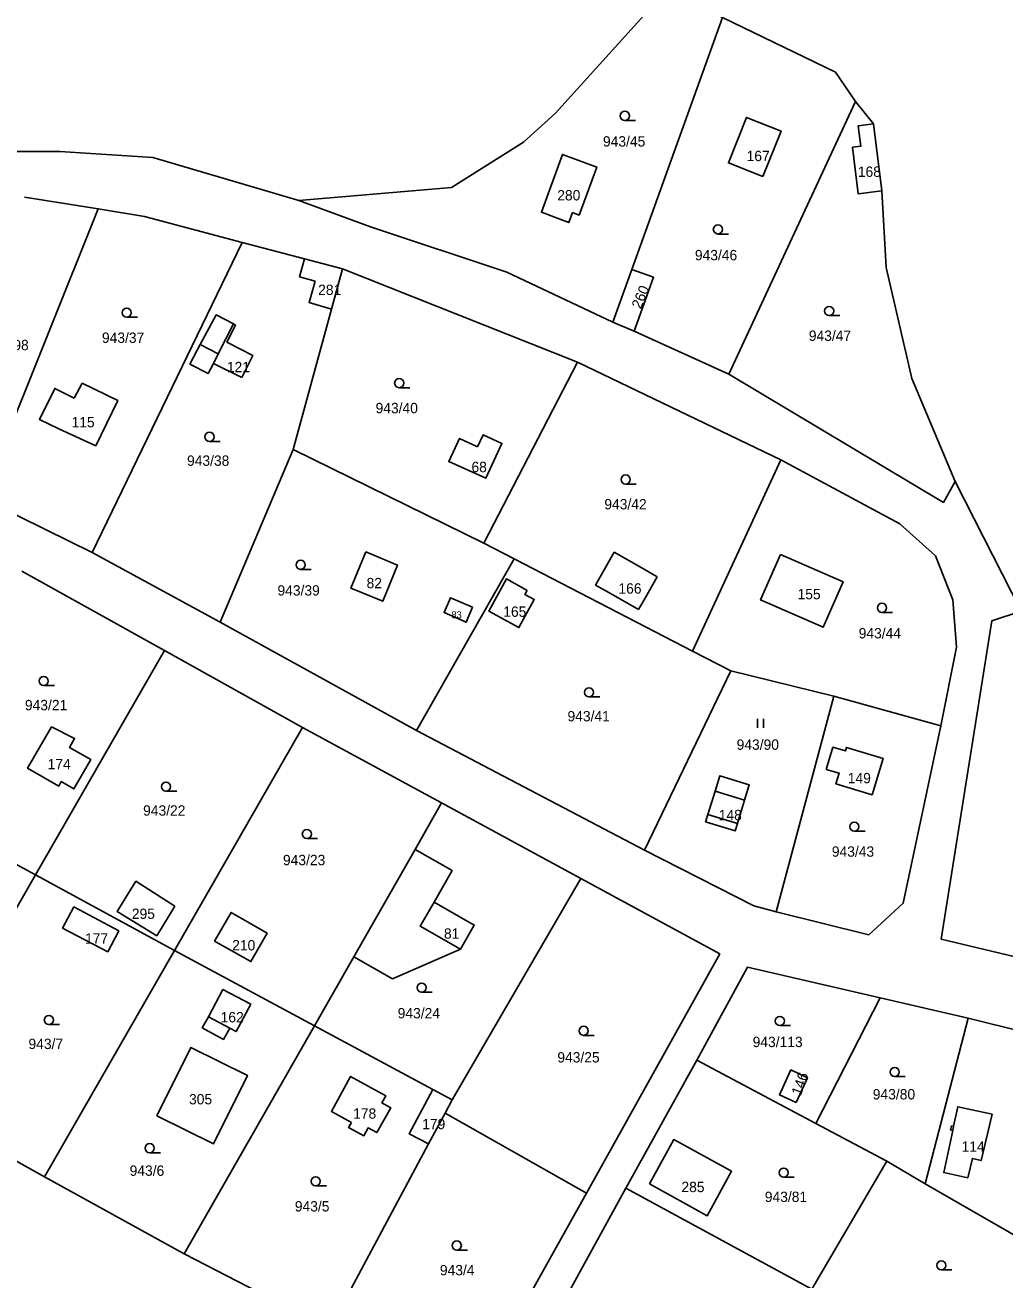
# Model space of a CAD drawing. Extents: x -7476540 to -746055, y -11317203 to -1129777.
# Drawn here: x -750806.6 to -750645.6, y -1131103.6 to -1130897.4 of the extents above; entities that cross this region are included whole.
import ezdxf

# ---------------------------------------------------------------- set-up
doc = ezdxf.new("R2010")
doc.units = 0
for name, color, linetype in [('Hranice parcel', 7, 'Continuous'), ('Parcelní čísla', 7, 'Continuous'), ('Vnitřní kresba', 7, 'Continuous'), ('Značky kultur', 7, 'Continuous')]:
    doc.layers.add(name, color=color, linetype=linetype)

msp = doc.modelspace()

# ---------------------------------------------------------------- linework, layer by layer
at = {"layer": 'Hranice parcel'}
for p, q in [((-750706.94, -1130937.58), (-750692.03, -1130896.19)), ((-750690.96, -1130954.78), (-750670.18, -1130909.99)), ((-750670.18, -1130909.99), (-750667.24, -1130913.65)), ((-750665.85, -1130924.67), (-750667.24, -1130913.65)), ((-750806.68, -1130925.7), (-750794.6, -1130927.65)), ((-750794.6, -1130927.65), (-750813.68, -1130975.17)), ((-750795.61, -1130984.09), (-750770.94, -1130933.18)), ((-750760.71, -1130935.83), (-750770.94, -1130933.18)), ((-750761.51, -1130938.81), (-750760.71, -1130935.83)), ((-750760.71, -1130935.83), (-750754.45, -1130937.46)), ((-750754.45, -1130937.46), (-750756.27, -1130944.11)), ((-750715.82, -1130952.81), (-750754.45, -1130937.46)), ((-750706.94, -1130937.58), (-750710.06, -1130946.23)), ((-750758.93, -1130939.53), (-750761.51, -1130938.81)), ((-750762.58, -1130967.16), (-750756.27, -1130944.11)), ((-750710.06, -1130946.23), (-750706.56, -1130947.73)), ((-750706.56, -1130947.73), (-750690.96, -1130954.78)), ((-750731.22, -1130982.55), (-750715.82, -1130952.81)), ((-750682.42, -1130968.89), (-750715.82, -1130952.81)), ((-750774.54, -1130995.56), (-750762.58, -1130967.16)), ((-750731.22, -1130982.55), (-750762.58, -1130967.16)), ((-750696.93, -1131000.31), (-750682.42, -1130968.89)), ((-750653.79, -1130972.43), (-750642.94, -1130993.73)), ((-750813.68, -1130975.17), (-750795.61, -1130984.09)), ((-750726.28, -1130985.14), (-750731.22, -1130982.55)), ((-750795.61, -1130984.09), (-750774.54, -1130995.56)), ((-750742.3, -1131013.32), (-750726.28, -1130985.14)), ((-750696.93, -1131000.31), (-750726.28, -1130985.14)), ((-750783.73, -1131000.19), (-750807.12, -1130987.17)), ((-750774.54, -1130995.56), (-750742.3, -1131013.32)), ((-750804.91, -1131037.07), (-750783.73, -1131000.19)), ((-750761.01, -1131012.83), (-750783.73, -1131000.19)), ((-750690.68, -1131003.53), (-750696.93, -1131000.31)), ((-750704.84, -1131033.01), (-750690.68, -1131003.53)), ((-750690.68, -1131003.53), (-750673.71, -1131007.69)), ((-750673.71, -1131007.69), (-750683.19, -1131043.14)), ((-750656.17, -1131012.57), (-750673.71, -1131007.69)), ((-750782.06, -1131049.49), (-750761.01, -1131012.83)), ((-750738.17, -1131025.24), (-750761.01, -1131012.83)), ((-750742.3, -1131013.32), (-750704.84, -1131033.01)), ((-750673.91, -1131016.08), (-750675, -1131019.76)), ((-750804.91, -1131037.07), (-750827.77, -1131024.65)), ((-750742.53, -1131032.88), (-750738.17, -1131025.24)), ((-750715.32, -1131037.65), (-750738.17, -1131025.24)), ((-750742.53, -1131032.88), (-750752.59, -1131050.52)), ((-750804.91, -1131037.07), (-750826.11, -1131074)), ((-750782.06, -1131049.49), (-750804.91, -1131037.07)), ((-750736.43, -1131074.01), (-750715.32, -1131037.65)), ((-750782.06, -1131049.49), (-750803.42, -1131086.7)), ((-750759.06, -1131061.85), (-750782.06, -1131049.49)), ((-750759.06, -1131061.85), (-750752.59, -1131050.52)), ((-750666.13, -1131057.26), (-750676.67, -1131077.92)), ((-750666.13, -1131057.26), (-750651.64, -1131060.63)), ((-750651.64, -1131060.63), (-750658.73, -1131087.82)), ((-750759.06, -1131061.85), (-750780.46, -1131099.34)), ((-750739.59, -1131072.31), (-750759.06, -1131061.85)), ((-750707.9, -1131088.56), (-750696.26, -1131067.52)), ((-750676.67, -1131077.92), (-750696.26, -1131067.52)), ((-750736.43, -1131074.01), (-750739.59, -1131072.31)), ((-750826.11, -1131074), (-750803.42, -1131086.7)), ((-750736.43, -1131074.01), (-750737.61, -1131076.21)), ((-750737.61, -1131076.21), (-750740.31, -1131081.25)), ((-750714.39, -1131089.36), (-750737.61, -1131076.21)), ((-750676.67, -1131077.92), (-750665.04, -1131084.1)), ((-750740.31, -1131081.25), (-750756.59, -1131111.62)), ((-750677.36, -1131105.16), (-750665.04, -1131084.1)), ((-750665.04, -1131084.1), (-750658.73, -1131087.82)), ((-750803.42, -1131086.7), (-750780.46, -1131099.34)), ((-750658.73, -1131087.82), (-750635.2, -1131101.36)), ((-750719.53, -1131109.68), (-750707.9, -1131088.56)), ((-750707.9, -1131088.56), (-750677.36, -1131105.16)), ((-750780.46, -1131099.34), (-750756.59, -1131111.62))]:
    msp.add_line(p, q, dxfattribs=at)
for points in [[(-750761.64, -1130926.26), (-750736.55, -1130924.13), (-750724.71, -1130916.65), (-750719.47, -1130911.9), (-750701.35, -1130891.83), (-750692.03, -1130896.19)], [(-750692.03, -1130896.19), (-750673.46, -1130905.17), (-750670.18, -1130909.99)], [(-750904.82, -1130906.58), (-750890.06, -1130908.85), (-750861.88, -1130910.89), (-750825.89, -1130918.18), (-750800.92, -1130918.19), (-750785.63, -1130919.17), (-750761.64, -1130926.26)], [(-750685.37, -1130922.33), (-750682.41, -1130914.86), (-750688.1, -1130912.61), (-750691.05, -1130920.07), (-750685.37, -1130922.33)], [(-750667.24, -1130913.65), (-750669.72, -1130913.96), (-750669.29, -1130917.34), (-750670.67, -1130917.5), (-750669.76, -1130925.14), (-750665.85, -1130924.67)], [(-750716.69, -1130928.25), (-750715.58, -1130928.65), (-750712.69, -1130920.76), (-750718.33, -1130918.68), (-750721.78, -1130928.15), (-750717.29, -1130929.88), (-750716.69, -1130928.25)], [(-750665.85, -1130924.67), (-750665.13, -1130937.25), (-750660.92, -1130955.49), (-750653.79, -1130972.43)], [(-750761.64, -1130926.26), (-750749.88, -1130930.57), (-750727.47, -1130938.05), (-750710.06, -1130946.23)], [(-750770.94, -1130933.18), (-750786.99, -1130928.86), (-750794.6, -1130927.65)], [(-750706.56, -1130947.73), (-750703.36, -1130938.87), (-750706.94, -1130937.58)], [(-750756.27, -1130944.11), (-750759.96, -1130943), (-750758.93, -1130939.53)], [(-750771, -1130955.32), (-750769.19, -1130951.74), (-750773.46, -1130949.52), (-750772.03, -1130946.72), (-750772.39, -1130946.53), (-750775.21, -1130945.05), (-750777.82, -1130949.92), (-750779.54, -1130953.14), (-750776.54, -1130954.7), (-750775.66, -1130953.05), (-750771, -1130955.32)], [(-750690.96, -1130954.78), (-750655.74, -1130975.85), (-750653.79, -1130972.43)], [(-750798.55, -1130958.74), (-750798.68, -1130958.67), (-750801.74, -1130957.13), (-750804.24, -1130962.26), (-750801.04, -1130963.75), (-750795.01, -1130966.55), (-750791.39, -1130959.14), (-750797.23, -1130956.29), (-750798.55, -1130958.74)], [(-750732.25, -1130966.73), (-750735.23, -1130965.35), (-750737, -1130969.16), (-750730.9, -1130971.86), (-750728.26, -1130966.17), (-750731.33, -1130964.75), (-750732.25, -1130966.73)], [(-750656.17, -1131012.57), (-750653.56, -1130999.63), (-750654.19, -1130991.85), (-750657.02, -1130984.63), (-750662.89, -1130979.4), (-750682.42, -1130968.89)], [(-750750.65, -1130984), (-750753.08, -1130989.97), (-750747.85, -1130992.1), (-750745.43, -1130986.15), (-750750.65, -1130984)], [(-750702.74, -1130988.08), (-750705.39, -1130986.57), (-750709.81, -1130984.05), (-750712.87, -1130989.44), (-750710.72, -1130990.67), (-750705.8, -1130993.48)], [(-750682.52, -1130984.41), (-750685.78, -1130991.89), (-750675.46, -1130996.38), (-750672.21, -1130988.9), (-750682.52, -1130984.41)], [(-750724.09, -1130990.32), (-750727.53, -1130988.43), (-750730.43, -1130993.72), (-750725.48, -1130996.43), (-750722.95, -1130991.81), (-750724.48, -1130991.02), (-750724.09, -1130990.32)], [(-750705.8, -1130993.48), (-750704.66, -1130991.46), (-750703.45, -1130989.34), (-750702.74, -1130988.08)], [(-750733.11, -1130993.09), (-750736.72, -1130991.53), (-750737.78, -1130993.97), (-750734.13, -1130995.56), (-750733.11, -1130993.09)], [(-750642.94, -1130993.73), (-750647.77, -1130995.31), (-750656.09, -1131047.61), (-750622.78, -1131055.54)], [(-750802.29, -1131012.71), (-750798.48, -1131014.63), (-750799.33, -1131016.12), (-750795.83, -1131018.12), (-750798.58, -1131022.93), (-750800.66, -1131021.74), (-750801.08, -1131022.47), (-750806.2, -1131019.54), (-750802.29, -1131012.71)], [(-750683.19, -1131043.14), (-750667.98, -1131046.89), (-750662.32, -1131041.72), (-750656.17, -1131012.57)], [(-750675, -1131019.76), (-750672.85, -1131020.35), (-750673.39, -1131022.09), (-750667.46, -1131023.9), (-750665.65, -1131017.94), (-750671.64, -1131016.12), (-750671.81, -1131016.7), (-750673.91, -1131016.08)], [(-750694.79, -1131028.34), (-750689.92, -1131029.83), (-750689.56, -1131028.64), (-750688.39, -1131024.79), (-750687.62, -1131022.27), (-750692.47, -1131020.78), (-750693.25, -1131023.33), (-750694.42, -1131027.15), (-750694.79, -1131028.34)], [(-750752.59, -1131050.52), (-750746.25, -1131054.13), (-750735.08, -1131049.27), (-750732.82, -1131045.32), (-750739.42, -1131041.56), (-750736.45, -1131036.35), (-750742.53, -1131032.88)], [(-750683.19, -1131043.14), (-750686.87, -1131042.15), (-750704.84, -1131033.01)], [(-750782, -1131042.23), (-750784.98, -1131047.07), (-750791.46, -1131043.1), (-750788.41, -1131038.11), (-750782, -1131042.23)], [(-750714.39, -1131089.36), (-750692.47, -1131050.06), (-750715.32, -1131037.65)], [(-750798.61, -1131042.3), (-750800.45, -1131045.82), (-750793.02, -1131049.68), (-750791.23, -1131046.24), (-750798.61, -1131042.3)], [(-750775.51, -1131047.94), (-750769.51, -1131051.31), (-750766.84, -1131046.65), (-750772.73, -1131043.24), (-750775.51, -1131047.94)], [(-750696.26, -1131067.52), (-750687.94, -1131052.2), (-750666.13, -1131057.26)], [(-750777.52, -1131062.21), (-750774.03, -1131064.11), (-750772.97, -1131062.26), (-750771.94, -1131062.8), (-750769.53, -1131058.29), (-750774.13, -1131055.92), (-750776.5, -1131060.38), (-750777.52, -1131062.21)], [(-750635.2, -1131101.36), (-750630.48, -1131091.47), (-750623.21, -1131067.69), (-750651.64, -1131060.63)], [(-750784.95, -1131076.66), (-750779.37, -1131065.42), (-750770.09, -1131070), (-750775.67, -1131081.26), (-750784.95, -1131076.66)], [(-750679.91, -1131074.49), (-750682.68, -1131073.2), (-750680.78, -1131069.1), (-750678.05, -1131070.41), (-750679.91, -1131074.49)], [(-750752.99, -1131077.74), (-750753.45, -1131078.57), (-750750.97, -1131079.94), (-750750.25, -1131078.63), (-750748.84, -1131079.41), (-750746.51, -1131075.34), (-750747.99, -1131074.53), (-750747.34, -1131073.35), (-750753.13, -1131070.17), (-750756.29, -1131075.93), (-750752.99, -1131077.74)], [(-750739.59, -1131072.31), (-750743.52, -1131079.61), (-750740.31, -1131081.25)], [(-750647.72, -1131076.39), (-750653.36, -1131075.15), (-750654.05, -1131078.37), (-750654.39, -1131078.3), (-750654.54, -1131078.98), (-750654.19, -1131079.06)], [(-750654.19, -1131079.06), (-750655.67, -1131085.97), (-750651.73, -1131086.82), (-750650.97, -1131083.66), (-750649.55, -1131084), (-750647.72, -1131076.39)], [(-750704.03, -1131087.85), (-750694.53, -1131093.07), (-750690.52, -1131085.77), (-750700.04, -1131080.55), (-750704.03, -1131087.85)], [(-750756.59, -1131111.62), (-750759.02, -1131115.99), (-750736.32, -1131128.66), (-750714.39, -1131089.36)]]:
    msp.add_lwpolyline(points, dxfattribs=at)
at = {"layer": 'Vnitřní kresba'}
for p, q in [((-750774.87, -1130951.47), (-750772.39, -1130946.53)), ((-750777.82, -1130949.92), (-750774.87, -1130951.47)), ((-750775.66, -1130953.05), (-750774.87, -1130951.47)), ((-750693.25, -1131023.33), (-750688.39, -1131024.79)), ((-750694.42, -1131027.15), (-750689.56, -1131028.64)), ((-750772.97, -1131062.26), (-750776.5, -1131060.38)), ((-750654.05, -1131078.37), (-750654.19, -1131079.06))]:
    msp.add_line(p, q, dxfattribs=at)
msp.add_lwpolyline([(-750739.42, -1131041.56), (-750741.68, -1131045.51), (-750735.08, -1131049.27)], dxfattribs=at)
at = {"layer": 'Značky kultur'}
for p, q in [((-750708.07, -1130913.1), (-750706.32, -1130913.1)), ((-750692.78, -1130931.76), (-750691.03, -1130931.76)), ((-750789.91, -1130945.44), (-750788.16, -1130945.44)), ((-750674.5, -1130945.16), (-750672.75, -1130945.16)), ((-750745.14, -1130957.01), (-750743.39, -1130957.01)), ((-750776.31, -1130965.84), (-750774.56, -1130965.84)), ((-750707.94, -1130972.85), (-750706.19, -1130972.85)), ((-750761.34, -1130986.86), (-750759.59, -1130986.86)), ((-750665.83, -1130993.94), (-750664.08, -1130993.94)), ((-750803.55, -1131005.96), (-750801.8, -1131005.96)), ((-750713.95, -1131007.83), (-750712.2, -1131007.83)), ((-750686.29, -1131012.9), (-750686.29, -1131011.4)), ((-750685.29, -1131012.9), (-750685.29, -1131011.4)), ((-750783.45, -1131023.31), (-750781.7, -1131023.31)), ((-750670.35, -1131029.88), (-750668.6, -1131029.88)), ((-750760.31, -1131031.1), (-750758.56, -1131031.1)), ((-750741.45, -1131056.34), (-750739.7, -1131056.34)), ((-750802.7, -1131061.66), (-750800.95, -1131061.66)), ((-750682.61, -1131061.81), (-750680.86, -1131061.81)), ((-750714.85, -1131063.43), (-750713.1, -1131063.43)), ((-750663.74, -1131070.21), (-750661.99, -1131070.21)), ((-750786.13, -1131082.72), (-750784.38, -1131082.72)), ((-750681.98, -1131086.73), (-750680.23, -1131086.73)), ((-750758.86, -1131088.15), (-750757.11, -1131088.15)), ((-750735.68, -1131098.71), (-750733.93, -1131098.71)), ((-750656.07, -1131101.98), (-750654.32, -1131101.98))]:
    msp.add_line(p, q, dxfattribs=at)
for centre in [(-750708.07, -1130912.35), (-750692.78, -1130931.01), (-750674.5, -1130944.41), (-750789.91, -1130944.69), (-750745.14, -1130956.26), (-750776.31, -1130965.09), (-750707.94, -1130972.1), (-750761.34, -1130986.11), (-750665.83, -1130993.19), (-750803.55, -1131005.21), (-750713.95, -1131007.08), (-750783.45, -1131022.56), (-750760.31, -1131030.35), (-750670.35, -1131029.13), (-750741.45, -1131055.59), (-750802.7, -1131060.91), (-750682.61, -1131061.06), (-750714.85, -1131062.68), (-750663.74, -1131069.46), (-750786.13, -1131081.97), (-750681.98, -1131085.98), (-750758.86, -1131087.4), (-750735.68, -1131097.96), (-750656.07, -1131101.23)]:
    msp.add_circle(centre, 0.75, dxfattribs=at)

# ---------------------------------------------------------------- texts
at = {"layer": 'Parcelní čísla'}
for s, height, p in [('943/45', 1.7, (-750711.66, -1130917.39)), ('167', 1.7, (-750688.06, -1130919.79)), ('168', 1.7, (-750669.79, -1130922.37)), ('280', 1.7, (-750719.17, -1130926.24)), ('943/46', 1.7, (-750696.56, -1130936.08)), ('281', 1.7, (-750758.46, -1130941.78)), ('943/37', 1.7, (-750793.98, -1130949.65)), ('943/47', 1.7, (-750677.84, -1130949.32)), ('943/98', 1.7, (-750812.96, -1130950.85)), ('121', 1.7, (-750773.46, -1130954.47)), ('943/40', 1.7, (-750749.02, -1130961.21)), ('115', 1.7, (-750798.97, -1130963.52)), ('943/38', 1.7, (-750780, -1130969.85)), ('68', 1.7, (-750733.27, -1130970.89)), ('943/42', 1.7, (-750711.44, -1130977.01)), ('82', 1.7, (-750750.5, -1130989.97)), ('166', 1.7, (-750709.12, -1130990.85)), ('943/39', 1.7, (-750765.14, -1130991.17)), ('155', 1.7, (-750679.69, -1130991.78)), ('165', 1.7, (-750728.04, -1130994.66)), ('83', 1.14, (-750736.56, -1130994.9)), ('943/44', 1.7, (-750669.65, -1130998.21)), ('943/21', 1.7, (-750806.64, -1131010.01)), ('943/41', 1.7, (-750717.49, -1131011.84)), ('943/90', 1.7, (-750689.7, -1131016.51)), ('174', 1.7, (-750802.9, -1131019.71)), ('149', 1.7, (-750671.44, -1131022.01)), ('943/22', 1.7, (-750787.22, -1131027.33)), ('148', 1.7, (-750692.64, -1131028.08)), ('943/43', 1.7, (-750674.06, -1131034.08)), ('943/23', 1.7, (-750764.24, -1131035.47)), ('295', 1.7, (-750789.07, -1131044.3)), ('177', 1.7, (-750796.76, -1131048.36)), ('81', 1.7, (-750737.79, -1131047.55)), ('210', 1.7, (-750772.58, -1131049.47)), ('943/24', 1.7, (-750745.39, -1131060.64)), ('162', 1.7, (-750774.48, -1131061.3)), ('943/7', 1.7, (-750806.05, -1131065.68)), ('943/113', 1.7, (-750687.07, -1131065.36)), ('943/25', 1.7, (-750719.16, -1131067.89)), ('305', 1.7, (-750779.67, -1131074.77)), ('943/80', 1.7, (-750667.33, -1131073.96)), ('178', 1.7, (-750752.71, -1131077.12)), ('179', 1.7, (-750741.37, -1131078.85)), ('114', 1.7, (-750652.75, -1131082.55)), ('943/6', 1.7, (-750789.43, -1131086.51)), ('285', 1.7, (-750698.77, -1131089.19)), ('943/81', 1.7, (-750685.07, -1131090.81)), ('943/5', 1.7, (-750762.29, -1131092.37)), ('943/4', 1.7, (-750738.46, -1131102.86))]:
    msp.add_text(s, height=height, dxfattribs=at).set_placement(p)
for s, rotation, p in [('260', 67, (-750705.47, -1130944.18)), ('146', 70, (-750679.16, -1131073.45))]:
    msp.add_text(s, height=1.7, rotation=rotation, dxfattribs=at).set_placement(p)

doc.saveas('drawing.dxf')
